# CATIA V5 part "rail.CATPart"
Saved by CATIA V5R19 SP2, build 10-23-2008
Part number: rail
Bounding box of the stored display mesh (mm): x 0 to 500, y -30 to 20, z -200 to 30
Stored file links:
  D:\Dropbox\IAO_2011\MMS_GR2\IAO_2011_1521_alefevre\IAO_2011_1521_alefevre\rail.CATPart
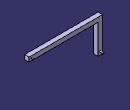
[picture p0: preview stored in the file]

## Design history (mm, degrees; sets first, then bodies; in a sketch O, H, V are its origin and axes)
Body1 (main body)
  Sketch1 on yz-plane, origin (0, 0, 0), H (0, 1, 0), V (0, 0, 1)
    point P2 (0, 0)
    line L1 (0, 0) -> (0, 30)
    line L2 (0, 30) -> (-30, 30)
    line L3 (0, 0) -> (-30, 0)
    line L4 (-30, 30) -> (-30, 0)
    length L2 = 30
    length L1 = 30
    vertical: L1 V, L4 V
    horizontal: L2 H, L3 H
    coincidence: P2 O
  Pad1: profile Sketch1, direction (1, 0, 0), length 500
  Sketch2 on face of Pad1 from Sketch1.L1, origin (0, 0, 0), H (-1, 0, 0), V (0, 0, 1)
    circle A1 centre (-480, 15) radius 5
    point P1 (-480, 15)
    reference projected line E1 (0, 30) -> (-500, 30) from edge [face of Pad1 from Sketch1.L2 | face of Pad1 from Sketch1.L1]
    reference projected line E2 (-500, 0) -> (-500, 30) from edge [face of Pad1 from Sketch1.L1 | end face of Pad1]
    radius A1 = 5
    distance P1 E1 = 15
    distance P1 E2 = 20
  Pad2: profile Sketch2, direction (0, 1, 0), length 10
  Sketch3 on face of Pad1 from Sketch1.L3, origin (0, 0, 0), H (1, 0, 0), V (0, -1, 0)
    point P1 (0, 30)
    line L1 (0, 30) -> (30, 30)
    line L2 (30, 30) -> (30, 0)
    line L3 (30, 0) -> (0, 0)
    line L4 (0, 0) -> (0, 30)
    reference projected line E1 (0, 0) -> (500, 0) from edge [face of Pad1 from Sketch1.L1 | face of Pad1 from Sketch1.L3]
    reference projected line E2 (0, 30) -> (500, 30) from edge [face of Pad1 from Sketch1.L3 | face of Pad1 from Sketch1.L4]
    length L1 = 30
    coincidence: P1 V, L3 E1, L1 E2
    horizontal: L1 H, L3 H
    vertical: L2 V, L4 V
  Pad3: profile Sketch3, direction (0, 0, -1), length 200
  Sketch4 on face of Pad3, origin (0, 0, 0), H (-1, 0, 0), V (0, 0, 1)
    circle A1 centre (-15, -180) radius 5
    point P1 (-15, -180)
    reference projected line E1 (0, -200) -> (-30, -200) from edge [face of Pad3 | end face of Pad3]
    reference projected line E2 (0, 0) -> (0, 30) from edge [face of Pad3 | face of Pad3]
    radius A1 = 5
    distance P1 E1 = 20
    distance P1 E2 = 15
  Pad4: profile Sketch4, direction (0, 1, 0), length 20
